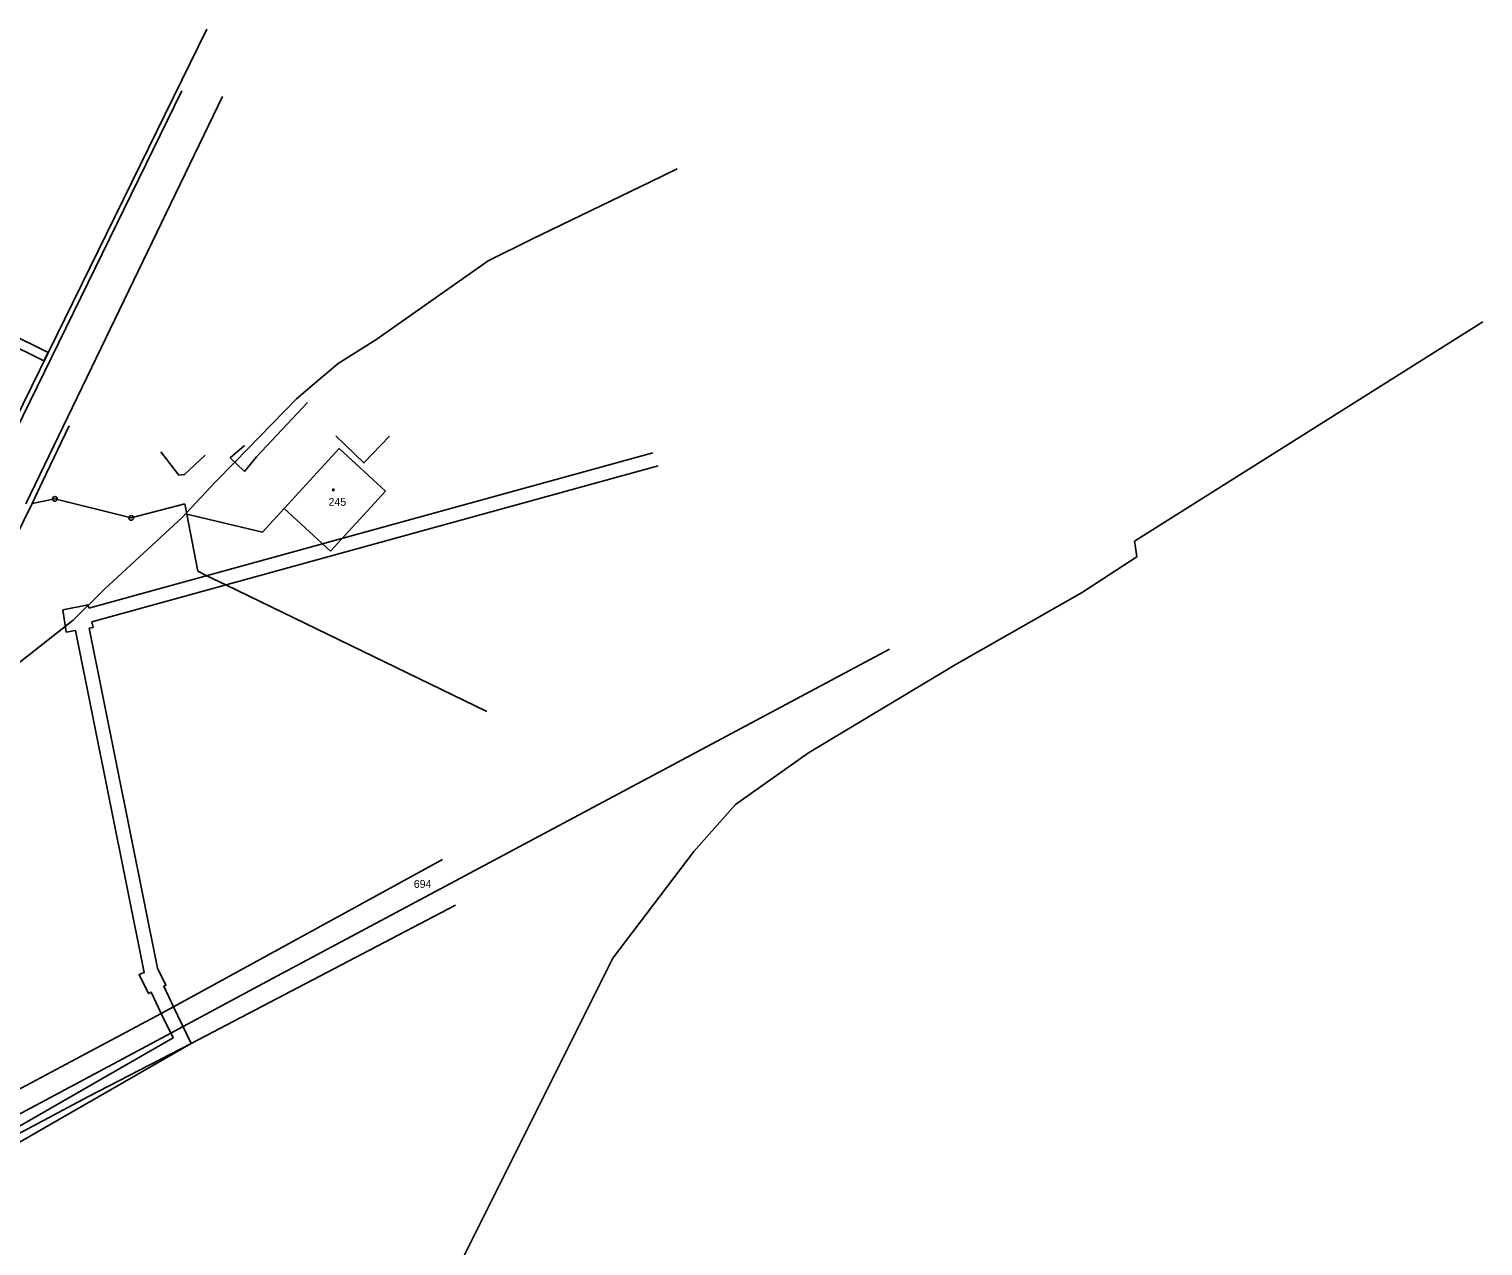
# Model space of a CAD drawing. Extents: x -747333 to -745433, y -1133152 to -1130600.
# Drawn here: x -745745.7 to -745432.9, y -1130885.6 to -1130623.8 of the extents above; entities that cross this region are included whole.
import ezdxf

# ---------------------------------------------------------------- set-up
doc = ezdxf.new("R2010")
doc.units = 0
for name, color, linetype in [('Vrstva 1', 7, 'Continuous'), ('Vrstva 10', 7, 'Continuous'), ('Vrstva 18', 7, 'Continuous'), ('Vrstva 19', 7, 'Continuous'), ('Vrstva 24', 7, 'Continuous'), ('Vrstva 25', 7, 'Continuous'), ('Vrstva 3', 7, 'Continuous'), ('Vrstva 30', 7, 'Continuous'), ('Vrstva 37', 7, 'Continuous'), ('Vrstva 4', 7, 'Continuous'), ('Vrstva 52', 7, 'Continuous')]:
    doc.layers.add(name, color=color, linetype=linetype)

msp = doc.modelspace()

# ---------------------------------------------------------------- linework, layer by layer
at = {"layer": 'Vrstva 1'}
for p, q in [((-745685.77, -1130704.14), (-745696.73, -1130715.84)), ((-745702.42, -1130716.03), (-745699.34, -1130713.4)), ((-745717.33, -1130714.75), (-745713.45, -1130719.78)), ((-745712.24, -1130719.61), (-745707.75, -1130715.45)), ((-745699.27, -1130718.97), (-745702.42, -1130716.03)), ((-745696.73, -1130715.84), (-745699.27, -1130718.97)), ((-745690.77, -1130726.92), (-745678.94, -1130714.05)), ((-745678.94, -1130714.05), (-745668.94, -1130723.24)), ((-745713.45, -1130719.78), (-745712.24, -1130719.61)), ((-745712.16, -1130725.97), (-745711.74, -1130728.17)), ((-745668.94, -1130723.24), (-745680.78, -1130736.15)), ((-745695.43, -1130732.03), (-745711.74, -1130728.17)), ((-745711.74, -1130728.17), (-745709.38, -1130740.46)), ((-745690.77, -1130726.92), (-745695.43, -1130732.03)), ((-745680.78, -1130736.15), (-745690.77, -1130726.92))]:
    msp.add_line(p, q, dxfattribs=at)
for points in [[(-745786.5, -1130785.08), (-745707.42, -1130623.78)], [(-745742.75, -1130721.13), (-745737.02, -1130709.14)], [(-745679.66, -1130711.35), (-745673.65, -1130717.14), (-745668.12, -1130711.4)], [(-745745.02, -1130725.89), (-745742.75, -1130721.13)], [(-745745.02, -1130725.89), (-745809.34, -1130856.84)], [(-745740.09, -1130724.89), (-745745.02, -1130725.89)], [(-745723.67, -1130728.98), (-745740.09, -1130724.89)], [(-745712.16, -1130725.97), (-745723.67, -1130728.98)], [(-745709.38, -1130740.46), (-745707.4, -1130741.42)], [(-745707.4, -1130741.42), (-745703.32, -1130743.4)], [(-745703.32, -1130743.4), (-745647.14, -1130770.65)], [(-745714.57, -1130834.16), (-745656.68, -1130802.49)], [(-745710.77, -1130842.09), (-745653.89, -1130812.32)], [(-745717.21, -1130835.6), (-745714.57, -1130834.16)], [(-745752.81, -1130854.59), (-745717.21, -1130835.6)], [(-745732.85, -1130853.52), (-745710.77, -1130842.09)], [(-745784.22, -1130880.84), (-745732.85, -1130853.52)]]:
    msp.add_lwpolyline(points, dxfattribs=at)
at = {"layer": 'Vrstva 10'}
for points in [[(-745695.44, -1130829.26), (-745560.54, -1130757.23)], [(-745712.53, -1130838.41), (-745695.44, -1130829.26)], [(-745715.18, -1130839.83), (-745712.53, -1130838.41)], [(-745763.92, -1130865.93), (-745715.18, -1130839.83)]]:
    msp.add_lwpolyline(points, dxfattribs=at)
at = {"layer": 'Vrstva 24'}
for p, q in [((-745740.14, -1130724.89), (-745740.04, -1130724.89)), ((-745723.72, -1130728.98), (-745723.62, -1130728.98))]:
    msp.add_line(p, q, dxfattribs=at)
for centre in [(-745740.09, -1130724.89), (-745723.67, -1130728.98)]:
    msp.add_circle(centre, 0.499289, dxfattribs=at)
at = {"layer": 'Vrstva 25'}
msp.add_circle((-745680.19, -1130722.95), 0.174503, dxfattribs=at)
at = {"layer": 'Vrstva 3'}
for points in [[(-745690.77, -1130726.92), (-745678.94, -1130714.05)], [(-745678.94, -1130714.05), (-745668.94, -1130723.24)], [(-745668.94, -1130723.24), (-745680.78, -1130736.15)], [(-745680.78, -1130736.15), (-745690.77, -1130726.92)]]:
    msp.add_lwpolyline(points, dxfattribs=at)
at = {"layer": 'Vrstva 30'}
for points in [[(-745919.16, -1130988.66), (-745930.99, -1131018.06), (-745931.27, -1131018.77), (-745933.27, -1131018.37), (-745932.78, -1131017.14), (-745921, -1130987.88), (-745902.24, -1130944.87), (-745878.06, -1130887.58), (-745853.31, -1130829.15), (-745833.47, -1130782.57), (-745813.85, -1130735.65), (-745786.7, -1130671.43), (-745744.58, -1130691.86), (-745741.56, -1130693.41), (-745742.44, -1130695.2), (-745745.48, -1130693.64), (-745785.68, -1130674.15), (-745812.01, -1130736.43), (-745831.63, -1130783.35), (-745851.47, -1130829.93), (-745876.22, -1130888.36), (-745900.4, -1130945.65), (-745919.16, -1130988.66)], [(-745732.8, -1130748.42), (-745611.44, -1130714.99)], [(-745610.34, -1130717.79), (-745732.13, -1130751.34)], [(-745738.36, -1130748.76), (-745732.97, -1130747.67), (-745732.8, -1130748.42)], [(-745717.21, -1130835.6), (-745719.37, -1130831.07), (-745719.93, -1130831.35), (-745722, -1130827.25), (-745720.88, -1130826.82), (-745735.66, -1130753.21), (-745737.66, -1130753.54), (-745738.36, -1130748.76)], [(-745732.13, -1130751.34), (-745731.85, -1130752.56), (-745732.7, -1130752.71), (-745718.01, -1130825.87)], [(-745718.01, -1130825.87), (-745716.21, -1130829.53), (-745716.68, -1130829.75), (-745714.57, -1130834.16), (-745717.21, -1130835.6)], [(-745784.22, -1130880.84), (-745714.68, -1130840.88), (-745717.21, -1130835.6), (-745714.57, -1130834.16), (-745710.77, -1130842.09), (-745732.85, -1130853.52), (-745784.22, -1130880.84)], [(-745784.22, -1130880.84), (-745732.85, -1130853.52), (-745710.77, -1130842.09), (-745782.58, -1130883.36)]]:
    msp.add_lwpolyline(points, dxfattribs=at)
at = {"layer": 'Vrstva 37'}
msp.add_circle((-745680.19, -1130722.95), 0.174503, dxfattribs=at)
at = {"layer": 'Vrstva 4'}
for points in [[(-745712.82, -1130637.07), (-745784.42, -1130783.53)], [(-745746.38, -1130725.93), (-745704.06, -1130638.3)]]:
    msp.add_lwpolyline(points, dxfattribs=at)
at = {"layer": 'Vrstva 52'}
for points in [[(-745759.56, -1130769.37), (-745736.13, -1130751), (-745729.37, -1130744.25), (-745712.75, -1130728.87), (-745711.8, -1130727.87), (-745705.56, -1130721.25), (-745701.4, -1130716.98), (-745688.13, -1130703.37), (-745684.25, -1130700.07), (-745679.19, -1130695.75), (-745671.06, -1130690.63), (-745646.88, -1130673.63), (-745637.5, -1130669), (-745611.98, -1130656.64), (-745606.26, -1130653.88)], [(-745754.44, -1131096.75), (-745742.12, -1131071.25), (-745734, -1131056), (-745727.25, -1131040.62), (-745720.87, -1131027.87), (-745707.25, -1130999.87), (-745682.56, -1130948.75), (-745677.06, -1130937.75), (-745674.94, -1130933.5), (-745620.06, -1130823.75), (-745602.63, -1130800.75), (-745593.69, -1130790.63), (-745577.94, -1130779.5), (-745546.06, -1130760.37), (-745519.25, -1130745.12), (-745507.37, -1130737.37), (-745507.71, -1130734.82), (-745507.81, -1130734), (-745432.88, -1130686.79)]]:
    msp.add_lwpolyline(points, dxfattribs=at)

# ---------------------------------------------------------------- texts
at = {"layer": 'Vrstva 18'}
msp.add_text('694', height=1.7, dxfattribs=at).set_placement((-745662.88, -1130808.6))
at = {"layer": 'Vrstva 19'}
msp.add_text('245', height=1.7, dxfattribs=at).set_placement((-745681.221545, -1130726.38))

doc.saveas('drawing.dxf')
